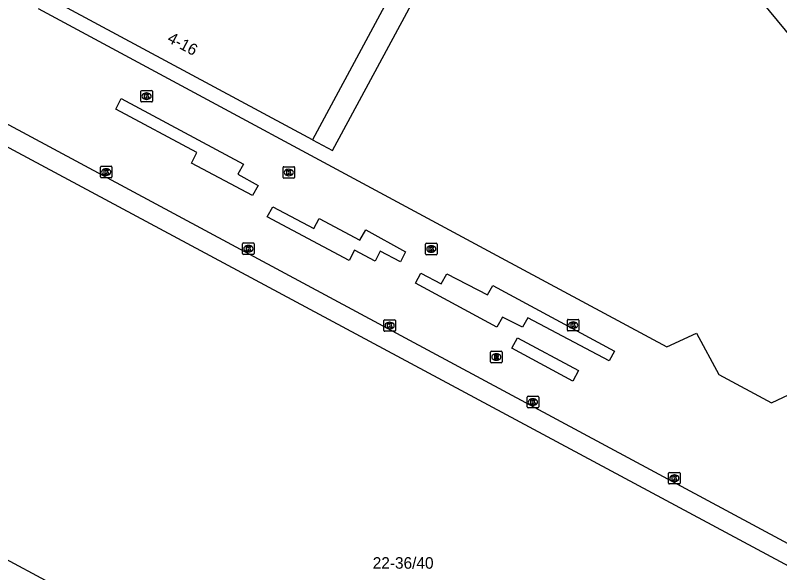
# Model space of a CAD drawing. Extents: x 159489 to 160304, y 383826 to 384530.
# Drawn here: x 159925.8 to 159992.1, y 384161.6 to 384209.9 of the extents above; entities that cross this region are included whole.
import ezdxf

# ---------------------------------------------------------------- set-up
doc = ezdxf.new("R2010")
doc.units = 0
for name, color, linetype in [('IMGEO_Kolk', 7, 'Continuous'), ('IMGEO_Pand', 7, 'Continuous'), ('IMGEO_Pand_nummerreeks', 7, 'Continuous'), ('IMGEO_Pand_overbouw', 7, 'Continuous'), ('IMGEO_Rioolput', 7, 'Continuous'), ('IMGEO_Voetpad_open', 7, 'Continuous')]:
    doc.layers.add(name, color=color, linetype=linetype)

msp = doc.modelspace()

# ---------------------------------------------------------------- linework, layer by layer
at = {"layer": 'IMGEO_Kolk'}
for p, q in [((159936.683, 384202.474), (159936.683, 384203.326)), ((159936.758, 384203.4), (159937.61, 384203.4)), ((159937.171, 384203.18), (159937.196, 384203.18)), ((159937.684, 384203.326), (159937.684, 384202.474)), ((159937.194, 384202.62), (159937.169, 384202.62)), ((159937.61, 384202.4), (159936.758, 384202.4)), ((159933.18, 384195.897), (159933.18, 384196.749)), ((159933.255, 384196.823), (159934.107, 384196.823)), ((159933.668, 384196.603), (159933.693, 384196.603)), ((159934.181, 384196.749), (159934.181, 384195.897)), ((159949.024, 384195.864), (159949.024, 384196.716)), ((159949.099, 384196.79), (159949.951, 384196.79)), ((159949.512, 384196.57), (159949.537, 384196.57)), ((159950.025, 384196.716), (159950.025, 384195.864)), ((159933.691, 384196.043), (159933.666, 384196.043)), ((159949.535, 384196.01), (159949.51, 384196.01)), ((159934.107, 384195.823), (159933.255, 384195.823)), ((159949.951, 384195.79), (159949.099, 384195.79)), ((159945.518, 384189.256), (159945.518, 384190.108)), ((159945.593, 384190.182), (159946.445, 384190.182)), ((159946.006, 384189.962), (159946.031, 384189.962)), ((159946.519, 384190.108), (159946.519, 384189.256)), ((159961.382, 384189.23), (159961.382, 384190.082)), ((159961.457, 384190.156), (159962.309, 384190.156)), ((159961.87, 384189.936), (159961.895, 384189.936)), ((159962.383, 384190.082), (159962.383, 384189.23)), ((159946.029, 384189.402), (159946.004, 384189.402)), ((159961.893, 384189.376), (159961.868, 384189.376)), ((159946.445, 384189.182), (159945.593, 384189.182)), ((159962.309, 384189.156), (159961.457, 384189.156)), ((159957.769, 384182.598), (159957.769, 384183.45)), ((159957.844, 384183.524), (159958.696, 384183.524)), ((159958.257, 384183.304), (159958.282, 384183.304)), ((159958.77, 384183.45), (159958.77, 384182.598)), ((159973.686, 384182.631), (159973.686, 384183.483)), ((159973.761, 384183.557), (159974.613, 384183.557)), ((159974.174, 384183.337), (159974.199, 384183.337)), ((159974.687, 384183.483), (159974.687, 384182.631)), ((159958.28, 384182.744), (159958.255, 384182.744)), ((159974.197, 384182.777), (159974.172, 384182.777)), ((159958.696, 384182.524), (159957.844, 384182.524)), ((159974.613, 384182.557), (159973.761, 384182.557)), ((159970.196, 384175.968), (159970.196, 384176.82)), ((159970.271, 384176.894), (159971.123, 384176.894)), ((159970.684, 384176.674), (159970.709, 384176.674)), ((159971.197, 384176.82), (159971.197, 384175.968)), ((159970.707, 384176.114), (159970.682, 384176.114)), ((159971.123, 384175.894), (159970.271, 384175.894)), ((159982.465, 384169.366), (159982.465, 384170.218)), ((159982.54, 384170.292), (159983.392, 384170.292)), ((159982.953, 384170.072), (159982.978, 384170.072)), ((159983.466, 384170.218), (159983.466, 384169.366)), ((159982.976, 384169.512), (159982.951, 384169.512)), ((159983.392, 384169.292), (159982.54, 384169.292))]:
    msp.add_line(p, q, dxfattribs=at)
for points in [[(159936.683, 384202.474), (159936.683, 384203.326)], [(159936.758, 384203.4), (159937.61, 384203.4)], [(159937.684, 384203.326), (159937.684, 384202.474)], [(159937.004, 384203.1), (159937.127, 384203.1), (159937.127, 384202.949), (159937.257, 384203.1), (159937.421, 384203.1), (159937.275, 384202.949), (159937.428, 384202.7), (159937.276, 384202.7), (159937.191, 384202.864), (159937.127, 384202.797), (159937.127, 384202.7), (159937.004, 384202.7), (159937.004, 384203.1)], [(159937.61, 384202.4), (159936.758, 384202.4)], [(159933.18, 384195.897), (159933.18, 384196.749)], [(159933.255, 384196.823), (159934.107, 384196.823)], [(159933.501, 384196.523), (159933.624, 384196.523), (159933.624, 384196.372), (159933.754, 384196.523), (159933.918, 384196.523), (159933.772, 384196.372), (159933.925, 384196.123), (159933.773, 384196.123), (159933.688, 384196.287), (159933.624, 384196.22), (159933.624, 384196.123), (159933.501, 384196.123), (159933.501, 384196.523)], [(159934.181, 384196.749), (159934.181, 384195.897)], [(159949.024, 384195.864), (159949.024, 384196.716)], [(159949.099, 384196.79), (159949.951, 384196.79)], [(159950.025, 384196.716), (159950.025, 384195.864)], [(159949.345, 384196.49), (159949.468, 384196.49), (159949.468, 384196.339), (159949.598, 384196.49), (159949.762, 384196.49), (159949.616, 384196.339), (159949.769, 384196.09), (159949.617, 384196.09), (159949.532, 384196.254), (159949.468, 384196.187), (159949.468, 384196.09), (159949.345, 384196.09), (159949.345, 384196.49)], [(159934.107, 384195.823), (159933.255, 384195.823)], [(159949.951, 384195.79), (159949.099, 384195.79)], [(159945.518, 384189.256), (159945.518, 384190.108)], [(159945.593, 384190.182), (159946.445, 384190.182)], [(159945.839, 384189.882), (159945.962, 384189.882), (159945.962, 384189.731), (159946.092, 384189.882), (159946.256, 384189.882), (159946.11, 384189.731), (159946.263, 384189.482), (159946.111, 384189.482), (159946.026, 384189.646), (159945.962, 384189.579), (159945.962, 384189.482), (159945.839, 384189.482), (159945.839, 384189.882)], [(159946.519, 384190.108), (159946.519, 384189.256)], [(159961.382, 384189.23), (159961.382, 384190.082)], [(159961.457, 384190.156), (159962.309, 384190.156)], [(159962.383, 384190.082), (159962.383, 384189.23)], [(159961.703, 384189.856), (159961.826, 384189.856), (159961.826, 384189.705), (159961.956, 384189.856), (159962.12, 384189.856), (159961.974, 384189.705), (159962.127, 384189.456), (159961.975, 384189.456), (159961.89, 384189.62), (159961.826, 384189.553), (159961.826, 384189.456), (159961.703, 384189.456), (159961.703, 384189.856)], [(159946.445, 384189.182), (159945.593, 384189.182)], [(159962.309, 384189.156), (159961.457, 384189.156)], [(159957.769, 384182.598), (159957.769, 384183.45)], [(159957.844, 384183.524), (159958.696, 384183.524)], [(159958.77, 384183.45), (159958.77, 384182.598)], [(159973.686, 384182.631), (159973.686, 384183.483)], [(159973.761, 384183.557), (159974.613, 384183.557)], [(159974.007, 384183.257), (159974.13, 384183.257), (159974.13, 384183.106), (159974.26, 384183.257), (159974.424, 384183.257), (159974.278, 384183.106), (159974.431, 384182.857), (159974.279, 384182.857), (159974.194, 384183.021), (159974.13, 384182.954), (159974.13, 384182.857), (159974.007, 384182.857), (159974.007, 384183.257)], [(159974.687, 384183.483), (159974.687, 384182.631)], [(159958.09, 384183.224), (159958.213, 384183.224), (159958.213, 384183.073), (159958.343, 384183.224), (159958.507, 384183.224), (159958.361, 384183.073), (159958.514, 384182.824), (159958.362, 384182.824), (159958.277, 384182.988), (159958.213, 384182.921), (159958.213, 384182.824), (159958.09, 384182.824), (159958.09, 384183.224)], [(159958.696, 384182.524), (159957.844, 384182.524)], [(159974.613, 384182.557), (159973.761, 384182.557)], [(159970.196, 384175.968), (159970.196, 384176.82)], [(159970.271, 384176.894), (159971.123, 384176.894)], [(159971.197, 384176.82), (159971.197, 384175.968)], [(159970.517, 384176.594), (159970.64, 384176.594), (159970.64, 384176.443), (159970.77, 384176.594), (159970.934, 384176.594), (159970.788, 384176.443), (159970.941, 384176.194), (159970.789, 384176.194), (159970.704, 384176.358), (159970.64, 384176.291), (159970.64, 384176.194), (159970.517, 384176.194), (159970.517, 384176.594)], [(159971.123, 384175.894), (159970.271, 384175.894)], [(159982.465, 384169.366), (159982.465, 384170.218)], [(159982.54, 384170.292), (159983.392, 384170.292)], [(159982.786, 384169.992), (159982.909, 384169.992), (159982.909, 384169.841), (159983.039, 384169.992), (159983.203, 384169.992), (159983.057, 384169.841), (159983.21, 384169.592), (159983.058, 384169.592), (159982.973, 384169.756), (159982.909, 384169.689), (159982.909, 384169.592), (159982.786, 384169.592), (159982.786, 384169.992)], [(159983.466, 384170.218), (159983.466, 384169.366)], [(159983.392, 384169.292), (159982.54, 384169.292)]]:
    msp.add_lwpolyline(points, dxfattribs=at)
for centre, start, end in [((159936.76, 384203.324), 91.55205, 178.44795), ((159936.76, 384203.324), 91.55205, 178.44795), ((159937.608, 384203.324), 1.55205, 88.44795), ((159937.608, 384203.324), 1.55205, 88.44795), ((159936.76, 384202.476), 181.55205, 268.44795), ((159936.76, 384202.476), 181.55205, 268.44795), ((159937.608, 384202.476), 271.55205, 358.44795), ((159937.608, 384202.476), 271.55205, 358.44795), ((159933.257, 384196.747), 91.55205, 178.44795), ((159933.257, 384196.747), 91.55205, 178.44795), ((159934.105, 384196.747), 1.55205, 88.44795), ((159934.105, 384196.747), 1.55205, 88.44795), ((159949.101, 384196.714), 91.55205, 178.44795), ((159949.101, 384196.714), 91.55205, 178.44795), ((159949.949, 384196.714), 1.55205, 88.44795), ((159949.949, 384196.714), 1.55205, 88.44795), ((159933.257, 384195.899), 181.55205, 268.44795), ((159933.257, 384195.899), 181.55205, 268.44795), ((159934.105, 384195.899), 271.55205, 358.44795), ((159934.105, 384195.899), 271.55205, 358.44795), ((159949.101, 384195.866), 181.55205, 268.44795), ((159949.101, 384195.866), 181.55205, 268.44795), ((159949.949, 384195.866), 271.55205, 358.44795), ((159949.949, 384195.866), 271.55205, 358.44795), ((159945.595, 384190.106), 91.55205, 178.44795), ((159945.595, 384190.106), 91.55205, 178.44795), ((159946.443, 384190.106), 1.55205, 88.44795), ((159946.443, 384190.106), 1.55205, 88.44795), ((159961.459, 384190.08), 91.55205, 178.44795), ((159961.459, 384190.08), 91.55205, 178.44795), ((159962.307, 384190.08), 1.55205, 88.44795), ((159962.307, 384190.08), 1.55205, 88.44795), ((159945.595, 384189.258), 181.55205, 268.44795), ((159945.595, 384189.258), 181.55205, 268.44795), ((159946.443, 384189.258), 271.55205, 358.44795), ((159946.443, 384189.258), 271.55205, 358.44795), ((159961.459, 384189.232), 181.55205, 268.44795), ((159961.459, 384189.232), 181.55205, 268.44795), ((159962.307, 384189.232), 271.55205, 358.44795), ((159962.307, 384189.232), 271.55205, 358.44795), ((159957.846, 384183.448), 91.55205, 178.44795), ((159957.846, 384183.448), 91.55205, 178.44795), ((159958.694, 384183.448), 1.55205, 88.44795), ((159958.694, 384183.448), 1.55205, 88.44795), ((159973.763, 384183.481), 91.55205, 178.44795), ((159973.763, 384183.481), 91.55205, 178.44795), ((159974.611, 384183.481), 1.55205, 88.44795), ((159974.611, 384183.481), 1.55205, 88.44795), ((159957.846, 384182.6), 181.55205, 268.44795), ((159957.846, 384182.6), 181.55205, 268.44795), ((159958.694, 384182.6), 271.55205, 358.44795), ((159958.694, 384182.6), 271.55205, 358.44795), ((159973.763, 384182.633), 181.55205, 268.44795), ((159973.763, 384182.633), 181.55205, 268.44795), ((159974.611, 384182.633), 271.55205, 358.44795), ((159974.611, 384182.633), 271.55205, 358.44795), ((159970.273, 384176.818), 91.55205, 178.44795), ((159970.273, 384176.818), 91.55205, 178.44795), ((159971.121, 384176.818), 1.55205, 88.44795), ((159971.121, 384176.818), 1.55205, 88.44795), ((159970.273, 384175.97), 181.55205, 268.44795), ((159970.273, 384175.97), 181.55205, 268.44795), ((159971.121, 384175.97), 271.55205, 358.44795), ((159971.121, 384175.97), 271.55205, 358.44795), ((159982.542, 384170.216), 91.55205, 178.44795), ((159982.542, 384170.216), 91.55205, 178.44795), ((159983.39, 384170.216), 1.55205, 88.44795), ((159983.39, 384170.216), 1.55205, 88.44795), ((159982.542, 384169.368), 181.55205, 268.44795), ((159982.542, 384169.368), 181.55205, 268.44795), ((159983.39, 384169.368), 271.55205, 358.44795), ((159983.39, 384169.368), 271.55205, 358.44795)]:
    msp.add_arc(centre, 0.0765, start, end, dxfattribs=at)
for centre, major_axis, ratio, start_param, end_param in [((159937.17, 384202.9), (-0.387, 0.002), 0.722429, 4.712389, 7.853982), ((159937.195, 384202.9), (-0.39, 0.002), 0.717154, 1.570796, 4.712389), ((159933.667, 384196.323), (-0.387, 0.002), 0.722429, 4.712389, 7.853982), ((159933.692, 384196.323), (-0.39, 0.002), 0.717154, 1.570796, 4.712389), ((159949.511, 384196.29), (-0.387, 0.002), 0.722429, 4.712389, 7.853982), ((159949.536, 384196.29), (-0.39, 0.002), 0.717154, 1.570796, 4.712389), ((159946.005, 384189.682), (-0.387, 0.002), 0.722429, 4.712389, 7.853982), ((159946.03, 384189.682), (-0.39, 0.002), 0.717154, 1.570796, 4.712389), ((159961.869, 384189.656), (-0.387, 0.002), 0.722429, 4.712389, 7.853982), ((159961.894, 384189.656), (-0.39, 0.002), 0.717154, 1.570796, 4.712389), ((159958.256, 384183.024), (-0.387, 0.002), 0.722429, 4.712389, 7.853982), ((159958.281, 384183.024), (-0.39, 0.002), 0.717154, 1.570796, 4.712389), ((159974.173, 384183.057), (-0.387, 0.002), 0.722429, 4.712389, 7.853982), ((159974.198, 384183.057), (-0.39, 0.002), 0.717154, 1.570796, 4.712389), ((159970.683, 384176.394), (-0.387, 0.002), 0.722429, 4.712389, 7.853982), ((159970.708, 384176.394), (-0.39, 0.002), 0.717154, 1.570796, 4.712389), ((159982.952, 384169.792), (-0.387, 0.002), 0.722429, 4.712389, 7.853982), ((159982.977, 384169.792), (-0.39, 0.002), 0.717154, 1.570796, 4.712389)]:
    msp.add_ellipse(centre, major_axis=major_axis, ratio=ratio, start_param=start_param, end_param=end_param, dxfattribs=at)
at = {"layer": 'IMGEO_Pand'}
for points in [[(159967.686, 384229.02), (159951.577, 384199.109), (159928.39, 384211.596)], [(159917.432, 384202.595), (159920.064, 384201.185), (160017.466, 384149)], [(160002.485, 384121.2), (159993.803, 384125.855), (159988.602, 384128.644), (159972.877, 384137.075), (159970.476, 384138.363), (159951.365, 384148.61), (159948.39, 384150.205), (159940.225, 384154.583), (159935.251, 384157.25), (159918.126, 384166.432), (159912.035, 384169.676), (159906.775, 384172.478), (159901.96, 384175.043), (159901.938, 384175.054)]]:
    msp.add_lwpolyline(points, dxfattribs=at)
at = {"layer": 'IMGEO_Pand_overbouw'}
msp.add_lwpolyline([(159953.299, 384198.181), (159969.896, 384228.943), (159943.238, 384243.325), (159926.605, 384212.558), (159928.39, 384211.596), (159944.07, 384240.7), (159944.524, 384241.543), (159945.039, 384241.265), (159967.686, 384229.02), (159951.577, 384199.109)], close=True, dxfattribs=at)
at = {"layer": 'IMGEO_Rioolput'}
for p, q in [((159967.023, 384179.869), (159967.023, 384180.721)), ((159967.098, 384180.795), (159967.95, 384180.795)), ((159968.024, 384180.721), (159968.024, 384179.869)), ((159967.534, 384180.015), (159967.509, 384180.015)), ((159967.511, 384180.575), (159967.536, 384180.575)), ((159967.95, 384179.795), (159967.098, 384179.795))]:
    msp.add_line(p, q, dxfattribs=at)
for points in [[(159967.023, 384179.869), (159967.023, 384180.721)], [(159967.098, 384180.795), (159967.95, 384180.795)], [(159968.024, 384180.721), (159968.024, 384179.869)], [(159967.612, 384180.493), (159967.36, 384180.495), (159967.36, 384180.095)], [(159967.36, 384180.095), (159967.484, 384180.095), (159967.484, 384180.257), (159967.495, 384180.257)], [(159967.538, 384180.414), (159967.484, 384180.414), (159967.484, 384180.333)], [(159967.484, 384180.333), (159967.536, 384180.333)], [(159967.542, 384180.228), (159967.613, 384180.095), (159967.753, 384180.095), (159967.688, 384180.221)], [(159967.95, 384179.795), (159967.098, 384179.795)]]:
    msp.add_lwpolyline(points, dxfattribs=at)
for centre, radius, start, end in [((159967.1, 384180.719), 0.0765, 91.55205, 178.44795), ((159967.1, 384180.719), 0.0765, 91.55205, 178.44795), ((159967.948, 384180.719), 0.0765, 1.55205, 88.44795), ((159967.948, 384180.719), 0.0765, 1.55205, 88.44795), ((159967.494, 384180.204), 0.0533, 26.02933, 88.69889), ((159967.52, 384180.522), 0.19, 274.7715, 282.96867), ((159967.544, 384180.318), 0.0964, 77.00612, 93.18647), ((159967.558, 384180.375), 0.0378, 276.66336, 79.67722), ((159967.611, 384180.383), 0.109, 350.36119, 89.41601), ((159967.609, 384180.383), 0.112, 277.58423, 350.98172), ((159967.593, 384180.168), 0.108, 29.51342, 73.79051), ((159967.1, 384179.871), 0.0765, 181.55205, 268.44795), ((159967.1, 384179.871), 0.0765, 181.55205, 268.44795), ((159967.948, 384179.871), 0.0765, 271.55205, 358.44795), ((159967.948, 384179.871), 0.0765, 271.55205, 358.44795)]:
    msp.add_arc(centre, radius, start, end, dxfattribs=at)
for centre, major_axis, ratio, start_param, end_param in [((159967.51, 384180.295), (-0.387, 0.002), 0.722429, 4.712389, 7.853982), ((159967.535, 384180.295), (-0.39, 0.002), 0.717154, 1.570796, 4.712389)]:
    msp.add_ellipse(centre, major_axis=major_axis, ratio=ratio, start_param=start_param, end_param=end_param, dxfattribs=at)
at = {"layer": 'IMGEO_Voetpad_open'}
for points in [[(159967.686, 384229.02), (159982.197, 384221.174), (160029.234, 384164.348)], [(159927.794, 384210.489), (159967.949, 384188.903), (159982.328, 384181.173), (159984.895, 384182.371), (159986.818, 384178.787), (159991.4, 384176.315), (159993.92, 384177.521), (159995.948, 384173.906), (160023.092, 384159.367)], [(159918.255, 384204.145), (160018.319, 384150.449)], [(159946.374, 384194.291), (159941.079, 384197.098), (159941.552, 384198.022), (159934.517, 384201.79), (159934.981, 384202.69), (159945.604, 384197.003), (159945.113, 384196.129), (159946.851, 384195.146), (159946.374, 384194.291)], [(159959.209, 384188.554), (159957.455, 384189.463), (159957.007, 384188.594), (159955.223, 384189.552), (159954.763, 384188.647), (159947.655, 384192.445), (159948.149, 384193.322), (159951.689, 384191.433), (159952.151, 384192.3), (159955.692, 384190.428), (159956.19, 384191.318), (159959.654, 384189.413), (159959.209, 384188.554)], [(159977.779, 384180.81), (159977.316, 384179.976), (159970.25, 384183.679), (159969.795, 384182.871), (159968.054, 384183.761), (159967.566, 384182.895), (159960.518, 384186.684), (159960.987, 384187.572), (159962.727, 384186.634), (159963.234, 384187.514), (159966.752, 384185.693), (159967.221, 384186.485), (159977.779, 384180.81)], [(159974.643, 384179.122), (159974.15, 384178.21), (159968.876, 384181.06), (159969.369, 384181.972), (159974.643, 384179.122)]]:
    msp.add_lwpolyline(points, dxfattribs=at)

# ---------------------------------------------------------------- texts
at = {"layer": 'IMGEO_Pand_nummerreeks'}
msp.add_text('4-16', height=1, rotation=331.69588, dxfattribs=at).set_placement((159938.905, 384207.637))
msp.add_text('22-36/40', height=1, dxfattribs=at).set_placement((159956.8, 384161.95))

doc.saveas('drawing.dxf')
